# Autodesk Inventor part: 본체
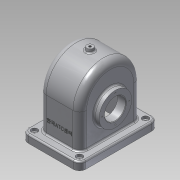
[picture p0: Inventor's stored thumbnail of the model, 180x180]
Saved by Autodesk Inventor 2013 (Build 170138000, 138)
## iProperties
Created: 2016-10
Part Number: 본체
Material: 알루미늄 6061
Document SubType Name: Modeling
Designer: Administrator
Density: 2.71 g/cm^3
Mass: 1216.77 g
Surface Area: 1195.34 cm^2
Volume: 448.993 cm^3
Author: Administrator
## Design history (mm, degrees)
sketch "스케치2"
  geometry: L1 (-38.5, 58)-(38.5, 58); L2 (38.5, 58)-(38.5, -58); L3 (38.5, -58)-(-38.5, -58); L4 (-38.5, -58)-(-38.5, 58); L5 (-38.5, 0)-(38.5, 0); L6 (0, 58)-(0, -58); 1 further point
  constraints: 12 end point, 4 midpoint, 3 perpendicular, 2 parallel, 1 horizontal
  dimensions: "d0" = 77 distance between parallel lines of L2 L4; "d2" = 0 distance from line of point (0, 0) L6; "d3" = 0 distance from line of point (0, 0) L5; "d6" = 38.5 distance between parallel lines of L4 L6 (= 0.5 x d0); "d7" = 58 distance between parallel lines of L5 L1; "d8" = 116 distance between parallel lines of L1 L3 (= 2 x d7)
extrude "돌출1" new body sketch "스케치2" distance "d9" = 80; taper "d10" = 0 deg
sketch "스케치3"
  geometry: L1 (-80, 0)-(-80, 116) reference; L2 (0, 0)-(-80, 0) reference; A1 r 52 centre (-80, 58) between (-80, 110) and (-80, 6); A2 r 58 centre (-80, 58) between (-80, 116) and (-80, 0); 1 further point
  constraints: 4 point on circle, 2 centre point, 2 end point, 2 point on line, 1 midpoint
  dimensions: "d11" = 104 diameter of A1
extrude "돌출2" join sketch "스케치3" stored distance "d15" = 80; taper "d16" = 0 deg
feature "쉘1" dims "d17" = 6
sketch "스케치4"
  geometry: L1 (-55, 75)-(55, 75); L2 (55, 75)-(55, -75); L3 (55, -75)-(-55, -75); L4 (-55, -75)-(-55, 75); L5 (-38.5, 58)-(38.5, 58); L6 (38.5, 58)-(38.5, -58); L7 (38.5, -58)-(-38.5, -58); L8 (-38.5, -58)-(-38.5, 58); L9 (0, 58)-(0, -58); L10 (-38.5, 0)-(38.5, 0); 1 further point
  constraints: 20 end point, 4 midpoint, 4 parallel, 2 horizontal, 2 perpendicular
  dimensions: "d18" = 110 distance between parallel lines of L2 L4; "d20" = 150 distance between parallel lines of L3 L1; "d21" = 55 distance between parallel lines of L2 L9 (= 0.5 x d18); "d22" = 75 distance between parallel lines of L3 L10 (= 0.5 x d20)
extrude "돌출3" join sketch "스케치4" distance "d23" = 15; taper "d24" = 0 deg
sketch "스케치5"
  geometry: L1 (80, -75)-(80, 75) reference; C1 r 20 at (15, 0); A1 r 58 centre (0, 0) between (0, 58) and (0, -58) reference; 1 further point
  constraints: 1 centre point
  dimensions: "d25" = 0 vertical distance of A1.centre C1.centre; "d26" = 65 distance from line of L1 C1.centre; "d27" = 40 diameter of C1
extrude "돌출4" cut sketch "스케치5" stored distance "d28" = 15; taper "d29" = 0 deg
sketch "스케치6"
  geometry: C1 r 20 at (15, 0) reference; C2 r 31 at (15, 0); 1 further point
  constraints: 1 centre point, 1 coincident
  dimensions: "d30" = 62 diameter of C2
extrude "돌출5" join sketch "스케치6" distance "d32" = 10; taper "d33" = 0 deg
sketch "스케치7"
  geometry: C1 r 20 at (-15, 0) reference; C2 r 37.5 at (-15, 0); 1 further point
  constraints: 1 centre point, 1 coincident
  dimensions: "d34" = 75 diameter of C2
extrude "돌출6" join sketch "스케치7" distance "d36" = 5; taper "d37" = 0 deg
node "작업 평면1"
sketch "스케치8"
  geometry: L1 (-32.5, 85)-(-32.5, 45) reference; L2 (-32.5, 65)-(-19.5, 65); L3 (-43.5, 45)-(-43.5, 85) reference; L4 (-32.5, 80)-(-32.5, 132) reference; L5 (-19.5, 65)-(-19.5, 93); L6 (-19.5, 93)-(-32.5, 103.908); L7 (-32.5, 103.908)-(-32.5, 65); 1 further point
  constraints: 8 end point, 1 collinear, 1 midpoint, 1 parallel, 1 perpendicular, 1 point on line
  dimensions: "d39" = 24 distance from line of L3 L2.end; "d40" = 28 distance of L2.end L5.end; "d41" = 50 deg angle of L6 L5
revolve "회전1" sketch "스케치8" stored, may be unused: angle "d42" = 90 deg
sketch "스케치9"
  geometry: C1 r 20 at (0, 0) reference; 1 further point
extrude "돌출7" cut sketch "스케치9" stored distance "d43" = 5; taper "d44" = 0 deg
fillet "모깎기1" dims "d45" = 12
fillet "모깎기2" dims "d46" = 3
sketch "스케치10"
  geometry: C1 r 6 at (-43, -63); C2 r 6 at (-43, 63); C3 r 6 at (43, 63); C4 r 6 at (43, -63); A1 r 9 centre (43, -63) between (43, -72) and (52, -63) reference; A2 r 9 centre (43, 63) between (52, 63) and (43, 72) reference; A3 r 9 centre (-43, 63) between (-43, 72) and (-52, 63) reference; A4 r 9 centre (-43, -63) between (-52, -63) and (-43, -72) reference; 1 further point
  constraints: 4 centre point, 4 coincident, 3 equal radius
  dimensions: "d47" = 12 diameter of C1
extrude "돌출8" cut sketch "스케치10" distance "d49" = 5; taper "d50" = 0 deg
sketch "스케치11"
  geometry: C1 r 6 at (0, 0) reference; C2 r 2.5 at (0, 0); C3 r 6 at (0, 126) reference; C4 r 6 at (86, 126) reference; C5 r 6 at (86, 0) reference; C6 r 2.5 at (0, 126); C7 r 2.5 at (86, 126); C8 r 2.5 at (86, 0); 1 further point
  constraints: 4 centre point, 4 coincident, 3 equal radius
  dimensions: "d51" = 5 diameter of C2
extrude "돌출9" cut sketch "스케치11" stored distance "d53" = 5; taper "d54" = 0 deg
fillet "모깎기3" dims "d55" = 13
fillet "모깎기4" dims "d56" = 3
chamfer "모따기1" distance "d57" = 1; stored, may be unused: second distance "d58" = 2, angle "d59" = 45 deg
fillet "모깎기5" dims "d60" = 8
sketch "스케치12"
  geometry: L1 (-2.004, -34.009)-(53.004, -34.009); L2 (53.004, -34.009)-(53.004, -45.991); L3 (53.004, -45.991)-(-2.004, -45.991); L4 (-2.004, -45.991)-(-2.004, -34.009); L5 (-2.004, -40)-(53.004, -40); L6 (25.5, -34.009)-(25.5, -45.991); L7 (51, 58)-(0, 58) reference; L8 (-17.5, -80)-(68.5, -80) reference; L9 (25.5, 58)-(25.5, -80)
  constraints: 6 end point, 5 midpoint, 1 perpendicular, 2 other
  dimensions: "d61" = 0 distance between parallel lines of L9 L6; "d63" = 40 distance between parallel lines of L8 L5
feature "엠보싱1" sketch "스케치12" dims "d0" = 77, "d2" = 0, "d3" = 0, "d6" = 38.5 (= 0.5 x d0), "d7" = 58, "d8" = 116 (= 2 x d7), "d64" = 0.5, "d65" = 0
fillet "모깎기6" dims "d66" = 3
node "작업 평면2"
sketch "스케치13"
  geometry: C1 r 6 at (0, 0); 1 further point
  constraints: 1 centre point, 1 coincident
  dimensions: "d68" = 12 diameter of C1
extrude "돌출10" join sketch "스케치13" stored distance "d70" = 5; taper "d71" = 10 deg
sketch "스케치14"
  geometry: C1 r 6 at (0, 0) reference
hole "구멍1" sketch "스케치14" at (0, 0) diameter "d72" = 4.459; stored, may be unused: countersink angle "d76" = 90 deg, drill point angle "d78" = 118 deg; dims "d73" = 6, "d74" = 4, "d75" = 2, "d77" = 8
fillet "모깎기7" dims "d79" = 3
sketch "스케치15" dims "d80" = 52
  geometry: C1 r 31 at (0, 0) reference; C2 r 21 at (0, 0) reference; C3 r 1.5 at (0, 26); 2 further points
  constraints: 2 vertical alignment, 1 centre point, 1 coincident, 2 other
  dimensions: "d83" = 3 diameter of C3
hole "구멍2" sketch "스케치15" at (0, 26) diameter "d84" = 2.459; stored, may be unused: countersink angle "d88" = 90 deg, drill point angle "d90" = 118 deg; dims "d85" = 6, "d86" = 4, "d87" = 2, "d89" = 8
sketch "스케치16" dims "d94" = 58
  geometry: C1 r 37.5 at (0, 0) reference; C2 r 21 at (0, 0) reference; C3 r 1.5 at (0, 29); 2 further points
  constraints: 2 vertical alignment, 1 centre point, 1 coincident, 2 other
  dimensions: "d96" = 3 diameter of C3
hole "구멍3" sketch "스케치16" at (0, 29) diameter "d97" = 2.459; stored, may be unused: countersink angle "d101" = 90 deg, drill point angle "d103" = 118 deg; dims "d98" = 6, "d99" = 4, "d100" = 2, "d102" = 8
node "솔리드1"
pattern_circular "원형 패턴1" dims angle "d92" = 360 deg
pattern_circular "원형 패턴2" dims angle "d105" = 360 deg
node "투영된 루프1"
other parameters: "d38" = 0, "d67" = 144
